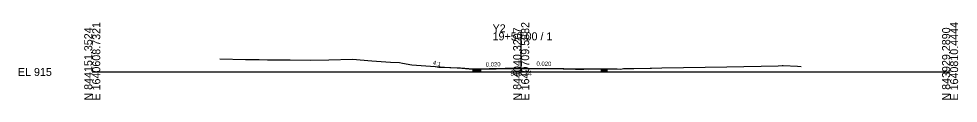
# Model space of a CAD drawing. Extents: x -26 to 303, y -10 to 8517.
# Drawn here: x -25.7 to 302.8, y 8490.3 to 8517.4 of the extents above; entities that cross this region are included whole.
import ezdxf

# ---------------------------------------------------------------- set-up
doc = ezdxf.new("R2010")
doc.units = 0
for name, color, linetype in [('Exist Cross Section Cell', 7, 'Continuous'), ('Exist XS Center Line Elevation Label', 7, 'Continuous'), ('Exist XS Ground Line', 7, 'Continuous'), ('Prop CMT Pvmt Course 1', 7, 'Continuous'), ('Prop CMT Pvmt Course 1 CG', 7, 'Continuous'), ('Prop CMT Pvmt Course 2', 7, 'Continuous'), ('Prop CMT Pvmt Course 3', 7, 'Continuous'), ('Prop CMT Pvmt Surface', 7, 'Continuous'), ('Prop CMT Slope Grass', 7, 'Continuous'), ('Prop CMT Subgrade Earthwork', 7, 'Continuous'), ('Prop XS SE Text', 7, 'Continuous'), ('Prop XS Side Slope Text', 7, 'Continuous')]:
    doc.layers.add(name, color=color, linetype=linetype)

msp = doc.modelspace()

# ---------------------------------------------------------------- linework, layer by layer
at = {"layer": 'Exist Cross Section Cell'}
for p, q in [((150, 8500), (150, 8513.88)), ((0, 8500), (150, 8500)), ((150, 8500), (300, 8500))]:
    msp.add_line(p, q, dxfattribs=at)
at = {"layer": 'Exist XS Ground Line'}
msp.add_lwpolyline([(44.59, 8504.63), (53.56, 8504.39), (57.35, 8504.31), (57.8, 8504.31), (58.36, 8504.31), (61.29, 8504.26), (69.2, 8504.2), (76.17, 8504.14), (82.71, 8504.26), (91.04, 8504.48), (97.79, 8503.95), (104.29, 8503.49), (107.48, 8503.32), (108.5, 8503.12), (111.81, 8502.47), (123.2, 8501.73), (127.62, 8501.46), (128.34, 8501.42), (129.21, 8501.34), (133.04, 8501.01), (133.69, 8500.87), (134.64, 8500.91), (135.66, 8500.96), (146.84, 8501.18), (149.84, 8501.24), (152.55, 8501.2), (164.71, 8501.07), (165.5, 8501.05), (167.08, 8501.05), (167.95, 8501.05), (169.02, 8501.04), (170.06, 8501.04), (171.9, 8501.04), (174.08, 8501.06), (177.45, 8501.08), (178.55, 8501.09), (180.05, 8501.08), (180.61, 8501.07), (181.82, 8501.06), (182.59, 8501.05), (183.52, 8501.05), (184.89, 8501.04), (185.75, 8501.19), (189.38, 8501.21), (195.08, 8501.31), (195.62, 8501.33), (199.14, 8501.4), (221.92, 8501.85), (239.82, 8502.19), (241.23, 8502.22), (241.63, 8502.22), (246.66, 8501.99), (247.88, 8501.91)], dxfattribs=at)
at = {"layer": 'Prop CMT Pvmt Course 1'}
msp.add_line((150.03, 8501.3), (179, 8501.13), dxfattribs=at)
for points in [[(150.03, 8501.3), (133.16, 8500.96)], [(133.16, 8500.96), (133.16, 8500.71)], [(133.16, 8500.71), (135.73, 8500.76)], [(150.03, 8501.05), (150.03, 8501.3)], [(150.03, 8501.05), (150.03, 8501.3)], [(180, 8500.86), (178, 8500.9)]]:
    msp.add_lwpolyline(points, dxfattribs=at)
msp.add_lwpolyline([(150.03, 8501.05), (150.03, 8501.18), (150.03, 8501.18), (150.03, 8501.05)], close=True, dxfattribs=at)
msp.add_lwpolyline([(150.03, 8501.05), (150.03, 8501.18), (150.03, 8501.18), (150.03, 8501.05)], close=True, dxfattribs=at)
at = {"layer": 'Prop CMT Pvmt Course 1 CG'}
msp.add_lwpolyline([(133.16, 8500.05), (133.16, 8500.38)], dxfattribs=at)
at = {"layer": 'Prop CMT Pvmt Course 2'}
for p, q in [((133.16, 8500.38), (135.73, 8500.43)), ((180, 8500.53), (178, 8500.57))]:
    msp.add_line(p, q, dxfattribs=at)
for points in [[(135.73, 8500.76), (133.16, 8500.71)], [(133.16, 8500.71), (133.16, 8500.46)], [(150.03, 8500.8), (150.03, 8501.05)], [(150.03, 8500.8), (150.03, 8501.05)], [(178, 8500.9), (179, 8500.88)]]:
    msp.add_lwpolyline(points, dxfattribs=at)
at = {"layer": 'Prop CMT Pvmt Course 3'}
for p, q in [((135.73, 8500.43), (133.16, 8500.38)), ((133.16, 8500.05), (135.48, 8500.09)), ((178, 8500.57), (179, 8500.55)), ((179, 8500.22), (178.48, 8500.23))]:
    msp.add_line(p, q, dxfattribs=at)
for points in [[(133.16, 8500.46), (133.16, 8500.09)], [(150.03, 8500.43), (150.03, 8500.8)], [(150.03, 8500.43), (150.03, 8500.8)]]:
    msp.add_lwpolyline(points, dxfattribs=at)
at = {"layer": 'Prop CMT Pvmt Surface'}
for p in [(150.03, 8501.3), (180, 8501.08)]:
    msp.add_line(p, (180, 8501.13), dxfattribs=at)
msp.add_lwpolyline([(150.03, 8501.3), (133.16, 8500.96)], dxfattribs=at)
at = {"layer": 'Prop CMT Slope Grass'}
for p, q in [((121.16, 8501.54), (119.41, 8501.97)), ((128.8, 8501.38), (121.16, 8501.54)), ((133.16, 8500.96), (128.8, 8501.38))]:
    msp.add_line(p, q, dxfattribs=at)
at = {"layer": 'Prop CMT Subgrade Earthwork'}
for p, q in [((133.16, 8500.05), (133.16, 8500.99)), ((135.73, 8500.1), (133.16, 8500.05)), ((135.73, 8500.95), (135.73, 8500.1)), ((178, 8501.09), (178, 8500.24)), ((178, 8500.24), (180, 8500.2)), ((180, 8501.08), (180, 8500.2))]:
    msp.add_line(p, q, dxfattribs=at)

# ---------------------------------------------------------------- texts
at = {"layer": 'Exist Cross Section Cell'}
for s, p in [('E 1640608.7321', (2.8, 8490)), ('E 1640709.5882', (152.8, 8490)), ('E 1640810.4444', (302.8, 8490)), ('N 844151.3524', (0, 8490)), ('N 844040.3207', (150, 8490)), ('N 843929.2890', (300, 8490))]:
    msp.add_text(s, height=2.8, rotation=90, dxfattribs=at).set_placement(p)
for s, p in [('Y2', (140, 8513.88)), ('19+50.00 / 1', (140, 8511.08)), ('EL 915', (-26, 8498.6))]:
    msp.add_text(s, height=2.8, dxfattribs=at).set_placement(p)
at = {"layer": 'Exist XS Center Line Elevation Label'}
msp.add_text('916.24', height=1.8, dxfattribs=at).set_placement((146.2, 8498.71))
at = {"layer": 'Prop XS SE Text'}
for rotation, p in [(1.1458, (137.63, 8501.88)), (358.8542, (155.35, 8502.19))]:
    msp.add_text('0.020', height=1.5, rotation=rotation, dxfattribs=at).set_placement(p)
at = {"layer": 'Prop XS Side Slope Text'}
msp.add_text('4:1', height=1.5, rotation=345.9492, dxfattribs=at).set_placement((118.98, 8502.63))

doc.saveas('drawing.dxf')
